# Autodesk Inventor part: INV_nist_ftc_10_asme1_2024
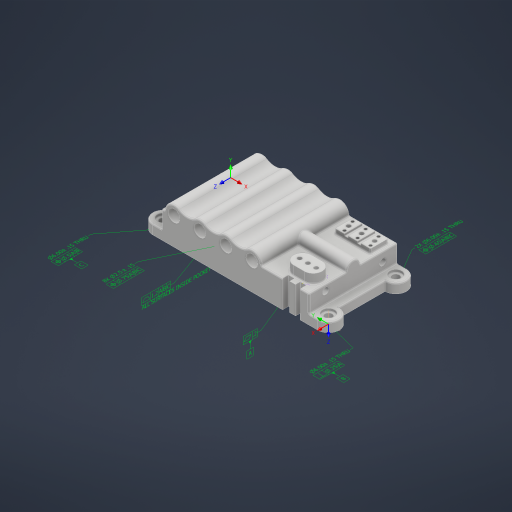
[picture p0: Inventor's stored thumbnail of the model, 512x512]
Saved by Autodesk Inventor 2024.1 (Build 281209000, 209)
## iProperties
Created: 2016-11
Part Number: INV_nist_ftc_10_asme1_2024
Material: Generic
Document SubType Name: Modeling
Designer: t_liuje
Density: 1 g/cm^3
Appearance: Default
Mass: 187.859 g
Surface Area: 487.851 cm^2
Volume: 187.859 cm^3
Author: t_liuje
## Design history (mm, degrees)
node "Tolerance Features"
  node "Planar Surface 1" dims "d273" = 6.78888 (derived), "d274" = 2.859 (derived), "d299" = 8.0955 (derived), "d300" = 2.22731 (derived), "d412" = 1.5 (derived), "d413" = 0 (derived), "d414" = 0 (derived), "d997" = -2.48442 (derived), "d998" = 10 (derived), "d999" = 0 (derived), "d1001" = 0.25 (derived), "d1002" = 0 (derived), "d1003" = 0 (derived), "d1004" = -22.09829 (derived), "d1005" = 10 (derived), "d1006" = 0 (derived), "d1008" = 0.5 (derived), "d1009" = 0 (derived), "d1010" = 0 (derived), "d1011" = -21.00192 (derived), "d1012" = 10 (derived), "d1013" = 0 (derived), "d1015" = 0.65 (derived), "d1016" = 0 (derived)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
  node "Datum Reference Frame 1"
  node "Simple Hole 1" dims "d273" = 6.78888 (derived), "d274" = 2.859 (derived), "d299" = 8.0955 (derived), "d300" = 2.22731 (derived), "d412" = 1.5 (derived), "d413" = 0 (derived), "d414" = 0 (derived), "d997" = -2.48442 (derived), "d998" = 10 (derived), "d999" = 0 (derived), "d1001" = 0.25 (derived), "d1002" = 0 (derived), "d1003" = 0 (derived), "d1004" = -22.09829 (derived), "d1005" = 10 (derived), "d1006" = 0 (derived), "d1008" = 0.5 (derived), "d1009" = 0 (derived), "d1010" = 0 (derived), "d1011" = -21.00192 (derived), "d1012" = 10 (derived), "d1013" = 0 (derived), "d1015" = 0.65 (derived), "d1016" = 0 (derived)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
  node "Datum Reference Frame 2"
  node "Simple Hole 2" dims "d273" = 6.78888 (derived), "d274" = 2.859 (derived), "d299" = 8.0955 (derived), "d300" = 2.22731 (derived), "d412" = 1.5 (derived), "d413" = 0 (derived), "d414" = 0 (derived), "d997" = -2.48442 (derived), "d998" = 10 (derived), "d999" = 0 (derived), "d1001" = 0.25 (derived), "d1002" = 0 (derived), "d1003" = 0 (derived), "d1004" = -22.09829 (derived), "d1005" = 10 (derived), "d1006" = 0 (derived), "d1008" = 0.5 (derived), "d1009" = 0 (derived), "d1010" = 0 (derived), "d1011" = -21.00192 (derived), "d1012" = 10 (derived), "d1013" = 0 (derived), "d1015" = 0.65 (derived), "d1016" = 0 (derived)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
  node "Datum Reference Frame 3"
  node "General Group 1"
  node "Coplanar Group 1" dims "d273" = 6.78888 (derived), "d274" = 2.859 (derived), "d299" = 8.0955 (derived), "d300" = 2.22731 (derived), "d412" = 1.5 (derived), "d413" = 0 (derived), "d414" = 0 (derived), "d997" = -2.48442 (derived), "d998" = 10 (derived), "d999" = 0 (derived), "d1001" = 0.25 (derived), "d1002" = 0 (derived), "d1003" = 0 (derived), "d1004" = -22.09829 (derived), "d1005" = 10 (derived), "d1006" = 0 (derived), "d1008" = 0.5 (derived), "d1009" = 0 (derived), "d1010" = 0 (derived), "d1011" = -21.00192 (derived), "d1012" = 10 (derived), "d1013" = 0 (derived), "d1015" = 0.65 (derived), "d1016" = 0 (derived)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
  node "Datum Reference Frame 4"
  node "Datum Reference Frame 5"
  node "Simple Hole 13" dims "d273" = 6.78888 (derived), "d274" = 2.859 (derived), "d299" = 8.0955 (derived), "d300" = 2.22731 (derived), "d412" = 1.5 (derived), "d413" = 0 (derived), "d414" = 0 (derived), "d997" = -2.48442 (derived), "d998" = 10 (derived), "d999" = 0 (derived), "d1001" = 0.25 (derived), "d1002" = 0 (derived), "d1003" = 0 (derived), "d1004" = -22.09829 (derived), "d1005" = 10 (derived), "d1006" = 0 (derived), "d1008" = 0.5 (derived), "d1009" = 0 (derived), "d1010" = 0 (derived), "d1011" = -21.00192 (derived), "d1012" = 10 (derived), "d1013" = 0 (derived), "d1015" = 0.65 (derived), "d1016" = 0 (derived)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
  node "Datum Reference Frame 6"
  node "Datum Reference Frame 12"
  node "Simple Hole 14" dims "d273" = 6.78888 (derived), "d274" = 2.859 (derived), "d299" = 8.0955 (derived), "d300" = 2.22731 (derived), "d412" = 1.5 (derived), "d413" = 0 (derived), "d414" = 0 (derived), "d997" = -2.48442 (derived), "d998" = 10 (derived), "d999" = 0 (derived), "d1001" = 0.25 (derived), "d1002" = 0 (derived), "d1003" = 0 (derived), "d1004" = -22.09829 (derived), "d1005" = 10 (derived), "d1006" = 0 (derived), "d1008" = 0.5 (derived), "d1009" = 0 (derived), "d1010" = 0 (derived), "d1011" = -21.00192 (derived), "d1012" = 10 (derived), "d1013" = 0 (derived), "d1015" = 0.65 (derived), "d1016" = 0 (derived)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
  node "Datum Reference Frame 7"
  node "Datum Reference Frame 18"
  node "Datum Reference Frame 23"
  node "Datum Reference Frame 13"
  node "Simple Hole 15" dims "d273" = 6.78888 (derived), "d274" = 2.859 (derived), "d299" = 8.0955 (derived), "d300" = 2.22731 (derived), "d412" = 1.5 (derived), "d413" = 0 (derived), "d414" = 0 (derived), "d997" = -2.48442 (derived), "d998" = 10 (derived), "d999" = 0 (derived), "d1001" = 0.25 (derived), "d1002" = 0 (derived), "d1003" = 0 (derived), "d1004" = -22.09829 (derived), "d1005" = 10 (derived), "d1006" = 0 (derived), "d1008" = 0.5 (derived), "d1009" = 0 (derived), "d1010" = 0 (derived), "d1011" = -21.00192 (derived), "d1012" = 10 (derived), "d1013" = 0 (derived), "d1015" = 0.65 (derived), "d1016" = 0 (derived)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
  node "Datum Reference Frame 8"
  node "Datum Reference Frame 19"
  node "Datum Reference Frame 14"
  node "Planar Surface 10" dims "d273" = 6.78888 (derived), "d274" = 2.859 (derived), "d299" = 8.0955 (derived), "d300" = 2.22731 (derived), "d412" = 1.5 (derived), "d413" = 0 (derived), "d414" = 0 (derived), "d997" = -2.48442 (derived), "d998" = 10 (derived), "d999" = 0 (derived), "d1001" = 0.25 (derived), "d1002" = 0 (derived), "d1003" = 0 (derived), "d1004" = -22.09829 (derived), "d1005" = 10 (derived), "d1006" = 0 (derived), "d1008" = 0.5 (derived), "d1009" = 0 (derived), "d1010" = 0 (derived), "d1011" = -21.00192 (derived), "d1012" = 10 (derived), "d1013" = 0 (derived), "d1015" = 0.65 (derived), "d1016" = 0 (derived)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
  node "Datum Reference Frame 9"
  node "Parallel Axes Pattern 3"
  node "Coplanar Group 2"
  node "Parallel Axes Pattern 5"
  node "Slot 1" dims "d273" = 6.78888 (derived), "d274" = 2.859 (derived), "d299" = 8.0955 (derived), "d300" = 2.22731 (derived), "d412" = 1.5 (derived), "d413" = 0 (derived), "d414" = 0 (derived), "d997" = -2.48442 (derived), "d998" = 10 (derived), "d999" = 0 (derived), "d1001" = 0.25 (derived), "d1002" = 0 (derived), "d1003" = 0 (derived), "d1004" = -22.09829 (derived), "d1005" = 10 (derived), "d1006" = 0 (derived), "d1008" = 0.5 (derived), "d1009" = 0 (derived), "d1010" = 0 (derived), "d1011" = -21.00192 (derived), "d1012" = 10 (derived), "d1013" = 0 (derived), "d1015" = 0.65 (derived), "d1016" = 0 (derived)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
  node "Datum Reference Frame 16"
  node "Datum Reference Frame 17"
  node "Slab 1"
  node "Parallel Axes Pattern 6"
  node "Cylindrical Surface 10"
  node "Simple Hole 51"
  node "Extruded Group 1"
  node "Simple Hole 63"
  node "Parallel Axes Pattern 12"
  node "Parallel Axes Pattern 13"
sketch "Sketch1"
  geometry: L1 (-62.5, 23)-(-62.5, 0); L2 (-62.5, 23)-(-22, 23); L3 (-62.5, 0)-(62.5, 0); L4 (62.5, 23)-(60, 23); L5 (62.5, 0)-(62.5, 23); L6 (80.303, 0)-(-60.812, 0); L7 (0, 48.078)-(0, -29.626); C1 r 3.5 at (-14, 23); C2 r 3.5 at (8, 23); C3 r 3.5 at (30, 23); C4 r 3.5 at (52, 23); A1 r 8 centre (-14, 23) between (-9.707, 29.751) and (-22, 23); A2 r 12.5 centre (-3, 40.299) between (-9.707, 29.751) and (3.707, 29.751); A3 r 8 centre (8, 23) between (12.293, 29.751) and (3.707, 29.751); A4 r 12.5 centre (19, 40.299) between (12.293, 29.751) and (25.707, 29.751); A5 r 8 centre (30, 23) between (34.293, 29.751) and (25.707, 29.751); A6 r 12.5 centre (41, 40.299) between (34.293, 29.751) and (47.707, 29.751); A7 r 8 centre (52, 23) between (60, 23) and (47.707, 29.751); 1 further point
  constraints: 14 end point, 14 point on circle, 11 centre point, 8 equal radius, 7 point on line, 6 tangent, 4 coincident, 2 collinear, 2 horizontal, 2 vertical, 1 other
  dimensions: "d0" = 125 distance of L1.end L3.end; "d1" = 10.5 distance from line of L5 A7.centre; "d2" = 23 distance of L1.start L1.end; "d3" = 8 radius of A7; "d4" = 22 distance of C3.centre C4.centre (= d5); "d5" = 22 distance of A1.centre A3.centre; "d6" = 22 distance of C3.centre A3.centre (= d5); "d7" = 12.5 radius of A6; "d8" = 7 diameter of C4
extrude "Extrusion1" new body sketch "Sketch1" stored distance "d9" = 75; taper "d10" = 0 deg
sketch "Sketch2"
  geometry: L1 (125, 0)-(125, -75) reference; L2 (0, 0)-(125, 0) reference; L3 (0, -75)-(0, 0) reference; L4 (125, -75)-(0, -75) reference; L5 (125, 0)-(132.5, 0); L6 (132.5, -18)-(132.5, -57); L7 (132.5, -75)-(125, -75); L8 (125, -75)-(125, 0); L9 (0, 0)-(-7.5, 0); L10 (-7.5, -18)-(-7.5, -57); L11 (-7.5, -75)-(0, -75); L12 (0, -75)-(0, 0); A1 r 9 centre (132.5, -9) between (132.5, -18) and (132.5, 0); A2 r 9 centre (132.5, -66) between (132.5, -75) and (132.5, -57); A3 r 9 centre (-7.5, -9) between (-7.5, 0) and (-7.5, -18); A4 r 9 centre (-7.5, -66) between (-7.5, -57) and (-7.5, -75); 1 further point
  constraints: 16 end point, 8 point on circle, 4 centre point, 4 parallel, 4 point on line, 4 tangent, 3 equal radius, 2 collinear, 2 horizontal, 2 perpendicular
  dimensions: "d11" = 7.5 distance of L1.start L5.end; "d12" = 18 distance of L6.start L5.end; "d13" = 18 distance of L6.end L7.start
extrude "Extrusion2" join sketch "Sketch2" distance "d14" = 8; taper "d15" = 0 deg
sketch "Sketch3"
  geometry: L1 (21, -53.5)-(30, -53.5); L2 (30, -68.5)-(21, -68.5); L3 (40.5, -75)-(0, -75) reference; L4 (40.5, 0)-(40.5, -75) reference; A1 r 7.5 centre (30, -61) between (30, -68.5) and (30, -53.5); A2 r 7.5 centre (21, -61) between (21, -53.5) and (21, -68.5); 1 further point
  constraints: 4 end point, 4 point on circle, 4 tangent, 2 centre point, 1 horizontal, 1 parallel
  dimensions: "d16" = 9 distance of L2.start L2.end; "d17" = 15 distance of L1.end L2.start; "d18" = 6.5 distance between parallel lines of L3 L2; "d19" = 10.5 distance from line of L4 A1.centre
extrude "Extrusion3" join sketch "Sketch3" distance "d20" = 8; taper "d21" = 0 deg
sketch "Sketch4"
  geometry: L1 (33, -75)-(33, -70); L2 (33, -70)-(28, -70); L3 (28, -70)-(28, -74); L4 (28, -74)-(23, -74); L5 (23, -74)-(23, -70); L6 (23, -70)-(18, -70); L7 (18, -70)-(18, -75); L8 (18, -75)-(33, -75); L9 (40.5, -75)-(0, -75) reference; L10 (40.5, 0)-(40.5, -75) reference; 1 further point
  constraints: 16 end point, 5 perpendicular, 2 collinear, 2 point on line, 1 vertical
  dimensions: "d22" = 5 distance of L1.start L1.end; "d23" = 5 distance of L1.end L2.end; "d24" = 4 distance of L2.end L3.end; "d25" = 5 distance of L3.end L4.end; "d26" = 5 distance of L5.end L6.end; "d27" = 7.5 distance between parallel lines of L10 L1
extrude "Extrusion4" cut sketch "Sketch4" stored distance "d28" = 8; taper "d29" = 0 deg
sketch "Sketch5"
  geometry: L1 (7.5, -5)-(37.5, -5); L2 (37.5, -5)-(37.5, -20); L3 (37.5, -20)-(7.5, -20); L4 (7.5, -20)-(7.5, -5); L5 (0, 0)-(40.5, 0) reference; L6 (40.5, 0)-(40.5, -75) reference; 1 further point
  constraints: 8 end point, 2 parallel, 1 horizontal, 1 perpendicular
  dimensions: "d30" = 30 distance of L2.end L3.end; "d31" = 15 distance of L1.end L2.end; "d32" = 5 distance between parallel lines of L1 L5; "d33" = 3 distance between parallel lines of L2 L6
extrude "Extrusion5" join sketch "Sketch5" distance "d34" = 4; taper "d35" = 0 deg
sketch "Sketch6"
  geometry: L1 (7.5, -5)-(37.5, -5) reference; L2 (7.5, -20)-(7.5, -5) reference; L3 (37.5, -5)-(37.5, -20) reference; L4 (37.5, -20)-(7.5, -20) reference; L5 (15.5, -5)-(18.5, -5); L6 (18.5, -5)-(18.5, -20); L7 (18.5, -20)-(15.5, -20); L8 (15.5, -20)-(15.5, -5); L9 (26.5, -5)-(29.5, -5); L10 (29.5, -5)-(29.5, -20); L11 (29.5, -20)-(26.5, -20); L12 (26.5, -20)-(26.5, -5); 1 further point
  constraints: 16 end point, 4 parallel, 4 point on line, 2 horizontal, 2 perpendicular
  dimensions: "d36" = 3 distance between parallel lines of L10 L12; "d37" = 8 distance between parallel lines of L3 L10; "d38" = 8 distance between parallel lines of L12 L6; "d39" = 3 distance between parallel lines of L8 L6
extrude "Extrusion6" cut sketch "Sketch6" distance "d40" = 1.5; taper "d41" = 0 deg
sketch "Sketch7"
  geometry: L1 (0, 75)-(0, 0) reference; A1 r 6 centre (0, 37.5) between (0, 43.5) and (0, 31.5); 1 further point
  constraints: 2 point on circle, 2 point on line, 1 centre point, 1 midpoint
  dimensions: "d42" = 12 diameter of A1
extrude "Extrusion7" join sketch "Sketch7" stored distance "d43" = 1.5; taper "d44" = 0 deg
fillet "Fillet1" dims "d45" = 1
sketch "Sketch11"
  geometry: A1 r 9 centre (-132.5, -9) between (-132.5, 0) and (-132.5, -18) reference; 3 further points
  constraints: 2 coincident
hole "Hole2" sketch "Sketch11" diameter "d57" = 6; stored, may be unused: countersink angle "d61" = 90 deg, drill point angle "d63" = 0 deg; dims "d58" = 6, "d59" = 10, "d60" = 2, "d62" = 8
sketch "Sketch12"
  geometry: C1 r 3.5 at (-52, -23) reference; C2 r 3.5 at (-30, -23) reference; C3 r 3.5 at (-8, -23) reference; C4 r 3.5 at (14, -23) reference; 4 further points
  constraints: 4 coincident
hole "Hole6" sketch "Sketch12" diameter "d93" = 10; stored, may be unused: countersink angle "d97" = 90 deg, drill point angle "d99" = 0 deg; dims "d94" = 6, "d95" = 10, "d96" = 2, "d98" = 10
hole "Hole7" diameter "d102" = 3.5; stored, may be unused: countersink angle "d106" = 90 deg, drill point angle "d108" = 0 deg; dims "d100" = 14, "d101" = 8, "d103" = 6, "d104" = 10, "d105" = 2, "d107" = 10.25
pattern_linear "Rectangular Pattern1" dims "d111" = 7
sketch "Sketch15"
  geometry: L1 (37.5, -19)-(37.5, -6) reference; L2 (29.5, -20)-(36.5, -20) reference; L3 (29.5, -5)-(29.5, -20) reference; L4 (29.5, -5)-(29.5, -20) reference; L5 (29.5, -16.191)-(37.5, -16.191); L6 (33.5, -16.191)-(33.5, -8.753); L7 (29.5, -12.5)-(36.185, -12.5); L8 (29.5, -20)-(29.5, -5); 2 further points
  constraints: 8 end point, 2 midpoint, 2 point on line, 2 symmetric about line, 1 horizontal, 1 perpendicular, 1 vertical
  dimensions: "d121" = 2.4 distance from line of L1 point (35.1, -17.5); "d122" = 2.5 distance from line of L2 point (35.1, -17.5)
hole "Hole9" sketch "Sketch15" at (35.1, -17.5), (31.9, -7.5) diameter "d123" = 2.459; stored, may be unused: countersink angle "d127" = 90 deg, drill point angle "d129" = 118 deg; dims "d124" = 6, "d125" = 10, "d126" = 2, "d128" = 12
sketch "Sketch8"
  geometry: L1 (-12, -5.5)-(-90, -5.5); L2 (-90, -5.5)-(-90, 44.5); L3 (-90, 44.5)-(-12, 44.5); L4 (-12, 44.5)-(-12, -5.5); L5 (0, 0)-(0, 39) reference; L6 (-110, -18)-(0, -18) reference; 1 further point
  constraints: 8 end point, 2 parallel, 1 horizontal, 1 perpendicular
  dimensions: "d142" = 78 distance of L2.end L3.end; "d143" = 50 distance of L1.end L2.end; "d144" = 12 distance between parallel lines of L5 L4; "d145" = 12.5 distance between parallel lines of L1 L6
extrude "Extrusion8" cut sketch "Sketch8" distance "d146" = 17; taper "d147" = 0 deg
fillet "Fillet2" dims "d148" = 2
hole "Hole11" diameter "d151" = 2.5; stored, may be unused: countersink angle "d155" = 90 deg, drill point angle "d157" = 118 deg; dims "d149" = 22, "d150" = 18, "d152" = 6, "d153" = 10, "d154" = 2, "d156" = 12
pattern_linear "Rectangular Pattern3" dims "d160" = 22, "d163" = 31
hole "Hole12" diameter "d287" = 5.5; stored, may be unused: countersink angle "d291" = 90 deg, drill point angle "d293" = 118 deg; dims "d285" = 14, "d286" = 5, "d288" = 6, "d289" = 4, "d290" = 2, "d292" = 27.5
hole "Hole13" diameter "d330" = 5.5; stored, may be unused: countersink angle "d334" = 90 deg, drill point angle "d336" = 118 deg; dims "d328" = 8.062, "d329" = 12.54, "d331" = 6, "d332" = 4, "d333" = 2, "d335" = 35
workplane "Work Plane2"
sketch "Sketch9"
  geometry: L1 (-26.77, 0)-(-11.77, 0)
  constraints: 2 end point, 1 horizontal
  dimensions: "d370" = 15 distance of L1.start L1.end
workplane "Work Plane3"
workplane "Work Plane4"
workplane "Work Plane5"
workplane "Work Plane6"
workplane "Work Plane7"
workplane "Work Plane8"
fillet "Fillet3" dims "d870" = 0.15
sketch "Sketch30"
  geometry: 3 further points
sketch "Sketch28"
  geometry: L1 (0, 0)-(0, 39) reference; L2 (-110, -18)-(0, -18) reference; C1 r 1.25 at (-18, 4); 2 further points
  constraints: 1 centre point, 1 coincident
  dimensions: "d1520" = 18 distance from line of L1 point (-18, 4); "d1521" = 22 distance from line of L2 point (-18, 4); "d1522" = 2.5 diameter of C1
extrude "Extrusion13" cut sketch "Sketch28" stored distance "d1523" = 10; taper "d1524" = 0 deg
pattern_linear "Rectangular Pattern4" dims "d1527" = 22, "d1530" = 31
sketch "Sketch13"
  geometry: C1 r 3.5 at (14, 23) reference; C2 r 3.5 at (-8, 23) reference; C3 r 3.5 at (-30, 23) reference; C4 r 3.5 at (-52, 23) reference; 5 further points
  constraints: 4 coincident
hole "Hole14" sketch "Sketch13" diameter "d901" = 10; stored, may be unused: countersink angle "d905" = 90 deg, drill point angle "d907" = 0 deg; dims "d902" = 6, "d903" = 4, "d904" = 2, "d906" = 10
mirror "Mirror3"
sketch "Sketch14"
  geometry: C1 r 3 at (7.5, -9) reference; C2 r 3 at (-132.5, -9) reference; C3 r 3 at (-132.5, -9) reference; C4 r 3 at (7.5, -9) reference; C5 r 3 at (-132.5, -66) reference; C6 r 3 at (7.5, -66) reference; 5 further points
  constraints: 4 coincident
hole "Hole15" sketch "Sketch14" diameter "d908" = 10; stored, may be unused: countersink angle "d912" = 90 deg, drill point angle "d914" = 0 deg; dims "d909" = 6, "d910" = 4, "d911" = 2, "d913" = 2
fillet "Fillet4" dims "d875" = 0.2
sketch "Sketch16"
  geometry: L1 (26.5, -19)-(26.5, -6); L2 (7.5, -20)-(25.5, -20); L3 (29.5, -20)-(26.5, -20) reference; L4 (18.5, -20)-(26.5, -20) reference; L5 (26.5, -5)-(18.5, -5) reference; L6 (18.5, -5)-(18.5, -20) reference; 3 further points
  constraints: 4 end point
  dimensions: "d915" = 2.4 distance from line of L1 point (24.1, -17.5); "d916" = 2.5 distance from line of L2 point (24.1, -17.5); "d917" = 2.5 distance from line of L5 point (20.9, -7.5); "d918" = 2.4 distance from line of L6 point (20.9, -7.5)
hole "Hole16" sketch "Sketch16" at (24.1, -17.5), (20.9, -7.5) diameter "d919" = 2.459; stored, may be unused: countersink angle "d923" = 90 deg, drill point angle "d925" = 118 deg; dims "d920" = 6, "d921" = 4, "d922" = 2, "d924" = 12
sketch "Sketch17"
  geometry: L1 (37.5, -19)-(37.5, -6); L2 (29.5, -20)-(36.5, -20); L3 (29.5, -5)-(29.5, -20); L4 (29.5, -5)-(29.5, -20); L5 (29.5, -16.191)-(37.5, -16.191); L6 (33.5, -16.191)-(33.5, -8.753); L7 (29.5, -12.5)-(36.185, -12.5); L8 (29.5, -20)-(29.5, -5); L9 (15.5, -19)-(15.5, -6); L10 (7.5, -20)-(14.5, -20); L11 (29.5, -20)-(26.5, -20); L12 (7.5, -20)-(15.5, -20); L13 (15.5, -5)-(7.5, -5); L14 (7.5, -5)-(7.5, -20); L15 (15.5, -20)-(15.5, -5) reference; C1 r 1.75 at (22.5, -12.5); 7 further points
  constraints: 28 end point, 2 midpoint, 2 point on line, 2 symmetric about line, 1 centre point, 1 coincident, 1 horizontal, 1 perpendicular, 1 vertical
  dimensions: "d926" = 2.4 distance from line of L1 point (35.1, -17.5); "d927" = 2.5 distance from line of L2 point (35.1, -17.5); "d928" = 2.4 distance from line of L9 point (13.1, -17.5); "d929" = 2.5 distance from line of L10 point (13.1, -17.5); "d930" = 2.5 distance from line of L13 point (9.9, -7.5); "d931" = 2.4 distance from line of L14 point (9.9, -7.5); "d1066" = 3.5 diameter of C1 (derived)
hole "Hole17" sketch "Sketch17" diameter "d932" = 2.459; stored, may be unused: countersink angle "d936" = 90 deg, drill point angle "d938" = 118 deg; dims "d933" = 6, "d934" = 4, "d935" = 2, "d937" = 12
sketch "Sketch18" dims "d944" = 10
  geometry: L1 (29.5, -20)-(36.5, -20) reference; L2 (37.5, -19)-(37.5, -6) reference; C1 r 1.75 at (11.5, -12.5); C2 r 1.75 at (33.5, -12.5); 3 further points
  constraints: 2 centre point, 2 coincident, 1 horizontal, 2 other
  dimensions: "d112" = 7.5 distance from line of L1 point (33.5, -12.5); "d113" = 4 distance from line of L2 point (33.5, -12.5); "d941" = 11 distance of point (33.5, -12.5) point (22.5, -12.5); "d1056" = 3.5 diameter of C1; "d1069" = 3.5 diameter of C2
extrude "Extrusion10" cut sketch "Sketch18" distance "d1057" = 9.25; taper "d1058" = 0 deg
extrude "Extrusion11" cut sketch "Sketch17" distance "d1067" = 9.25; taper "d1068" = 0 deg
extrude "Extrusion12" cut sketch "Sketch18" distance "d1070" = 9.25; taper "d1071" = 0 deg
sketch "Sketch20"
  geometry: L1 (-1.061, 8)-(5.303, 8) reference; L2 (3.544, 8)-(-4.428, 8); L3 (-4.428, 8)-(-4.428, -0.058); L4 (-4.428, -0.058)-(3.544, -0.058); L5 (3.544, -0.058)-(3.544, 8); 1 further point
  constraints: 8 end point, 2 parallel, 1 horizontal, 1 perpendicular, 1 point on line
patch "Boundary Patch1" sketch "Sketch20"
sketch "Sketch21"
  geometry: L1 (7.5, 8)-(-5.303, 8) reference; L2 (-8.827, 0)-(18.436, 0) reference; L3 (-1.99, 8)-(4.804, 8); L4 (4.804, 8)-(4.804, 0); L5 (4.804, 0)-(-1.99, 0); L6 (-1.99, 0)-(-1.99, 8); 2 further points
  constraints: 8 end point, 2 parallel, 1 horizontal, 1 midpoint, 1 perpendicular, 1 point on line
patch "Boundary Patch2" sketch "Sketch21"
workplane "Work Plane10"
mirror "Mirror4"
mirror "Mirror5"
workpoint "Work Point1"
workaxis "Work Axis1"
workpoint "Work Point2"
workpoint "Work Point3"
workpoint "Work Point4"
sketch "Sketch27"
  geometry: 2 further points
sketch "Sketch29"
  geometry: C1 r 1.75 at (32.5, -61); C2 r 1.75 at (25.5, -61); C3 r 1.75 at (18.5, -61); 4 further points
  constraints: 3 centre point, 3 coincident
extrude "Extrusion14" cut sketch "Sketch29" stored distance "d1538" = 10; taper "d1539" = 0 deg
sketch "Sketch32"
  geometry: 3 further points
  constraints: 1 coincident
sketch "Sketch33"
  geometry: 4 further points
  constraints: 1 coincident
body "Solid1"
node "Annotations"
sketch "Sketch10"
  geometry: 1 further point
node "Projected Loop1"
body "Srf1"
body "Srf2"
body "Srf4"
body "Srf5"
patch "Boundary Patch3"
patch "Boundary Patch4"
node "Leader Text 3"
node "Leader Text 6"
node "General Note 1"
node "General Surface Profile Tolerance"
node "Hole Note 1" dims "d0" = 125
node "Feature Control Frame 31"
node "Datum Identifier 2" dims "d0" = 125, "d273" = 6.78888 (derived), "d274" = 2.859 (derived), "d299" = 8.0955 (derived), "d300" = 2.22731 (derived), "d412" = 1.5 (derived), "d413" = 0 (derived), "d414" = 0 (derived), "d997" = -2.48442 (derived), "d998" = 10 (derived), "d999" = 0 (derived), "d1001" = 0.25 (derived), "d1002" = 0 (derived), "d1003" = 0 (derived), "d1004" = -22.09829 (derived), "d1005" = 10 (derived), "d1006" = 0 (derived), "d1008" = 0.5 (derived), "d1009" = 0 (derived), "d1010" = 0 (derived), "d1011" = -21.00192 (derived), "d1012" = 10 (derived), "d1013" = 0 (derived), "d1015" = 0.65 (derived)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
node "Hole Note 2" dims "d0" = 125
node "Feature Control Frame 32"
node "Datum Identifier 3" dims "d0" = 125, "d273" = 6.78888 (derived), "d274" = 2.859 (derived), "d299" = 8.0955 (derived), "d300" = 2.22731 (derived), "d412" = 1.5 (derived), "d413" = 0 (derived), "d414" = 0 (derived), "d997" = -2.48442 (derived), "d998" = 10 (derived), "d999" = 0 (derived), "d1001" = 0.25 (derived), "d1002" = 0 (derived), "d1003" = 0 (derived), "d1004" = -22.09829 (derived), "d1005" = 10 (derived), "d1006" = 0 (derived), "d1008" = 0.5 (derived), "d1009" = 0 (derived), "d1010" = 0 (derived), "d1011" = -21.00192 (derived), "d1012" = 10 (derived), "d1013" = 0 (derived), "d1015" = 0.65 (derived)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
node "Simple Hole 3"
node "Simple Hole 4"
node "Parallel Axes Pattern 1"
node "Hole Note 3" dims "d0" = 125
node "Feature Control Frame 33"
node "Diameter Dimension 1" dims "d0" = 125, "d1089" = 3.5 (derived)
node "Feature Control Frame 40"
node "Datum Identifier 5" dims "d0" = 125, "d273" = 6.78888 (derived), "d274" = 2.859 (derived), "d299" = 8.0955 (derived), "d300" = 2.22731 (derived), "d412" = 1.5 (derived), "d413" = 0 (derived), "d414" = 0 (derived), "d997" = -2.48442 (derived), "d998" = 10 (derived), "d999" = 0 (derived), "d1001" = 0.25 (derived), "d1002" = 0 (derived), "d1003" = 0 (derived), "d1004" = -22.09829 (derived), "d1005" = 10 (derived), "d1006" = 0 (derived), "d1008" = 0.5 (derived), "d1009" = 0 (derived), "d1010" = 0 (derived), "d1011" = -21.00192 (derived), "d1012" = 10 (derived), "d1013" = 0 (derived), "d1015" = 0.65 (derived)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
node "Diameter Dimension 2" dims "d0" = 125, "d1099" = 3.5 (derived)
node "Feature Control Frame 41"
node "Datum Identifier 6" dims "d0" = 125, "d273" = 6.78888 (derived), "d274" = 2.859 (derived), "d299" = 8.0955 (derived), "d300" = 2.22731 (derived), "d412" = 1.5 (derived), "d413" = 0 (derived), "d414" = 0 (derived), "d997" = -2.48442 (derived), "d998" = 10 (derived), "d999" = 0 (derived), "d1001" = 0.25 (derived), "d1002" = 0 (derived), "d1003" = 0 (derived), "d1004" = -22.09829 (derived), "d1005" = 10 (derived), "d1006" = 0 (derived), "d1008" = 0.5 (derived), "d1009" = 0 (derived), "d1010" = 0 (derived), "d1011" = -21.00192 (derived), "d1012" = 10 (derived), "d1013" = 0 (derived), "d1015" = 0.65 (derived)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
node "Diameter Dimension 3" dims "d0" = 125, "d1109" = 3.5 (derived)
node "Feature Control Frame 42"
node "Datum Identifier 7" dims "d0" = 125, "d273" = 6.78888 (derived), "d274" = 2.859 (derived), "d299" = 8.0955 (derived), "d300" = 2.22731 (derived), "d412" = 1.5 (derived), "d413" = 0 (derived), "d414" = 0 (derived), "d997" = -2.48442 (derived), "d998" = 10 (derived), "d999" = 0 (derived), "d1001" = 0.25 (derived), "d1002" = 0 (derived), "d1003" = 0 (derived), "d1004" = -22.09829 (derived), "d1005" = 10 (derived), "d1006" = 0 (derived), "d1008" = 0.5 (derived), "d1009" = 0 (derived), "d1010" = 0 (derived), "d1011" = -21.00192 (derived), "d1012" = 10 (derived), "d1013" = 0 (derived), "d1015" = 0.65 (derived)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
node "Feature Control Frame 43"
node "Datum Identifier 8" dims "d0" = 125, "d273" = 6.78888 (derived), "d274" = 2.859 (derived), "d299" = 8.0955 (derived), "d300" = 2.22731 (derived), "d412" = 1.5 (derived), "d413" = 0 (derived), "d414" = 0 (derived), "d997" = -2.48442 (derived), "d998" = 10 (derived), "d999" = 0 (derived), "d1001" = 0.25 (derived), "d1002" = 0 (derived), "d1003" = 0 (derived), "d1004" = -22.09829 (derived), "d1005" = 10 (derived), "d1006" = 0 (derived), "d1008" = 0.5 (derived), "d1009" = 0 (derived), "d1010" = 0 (derived), "d1011" = -21.00192 (derived), "d1012" = 10 (derived), "d1013" = 0 (derived), "d1015" = 0.65 (derived)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
node "Planar Surface 13"
node "Planar Surface 14"
node "Feature Control Frame 45"
node "Leader Text 10"
node "Planar Surface 16"
node "Planar Surface 17"
node "Linear Dimension 1" dims "d0" = 125, "d1217" = 15 (derived)
node "Feature Control Frame 51"
node "Datum Identifier 11" dims "d0" = 125, "d273" = 6.78888 (derived), "d274" = 2.859 (derived), "d299" = 8.0955 (derived), "d300" = 2.22731 (derived), "d412" = 1.5 (derived), "d413" = 0 (derived), "d414" = 0 (derived), "d997" = -2.48442 (derived), "d998" = 10 (derived), "d999" = 0 (derived), "d1001" = 0.25 (derived), "d1002" = 0 (derived), "d1003" = 0 (derived), "d1004" = -22.09829 (derived), "d1005" = 10 (derived), "d1006" = 0 (derived), "d1008" = 0.5 (derived), "d1009" = 0 (derived), "d1010" = 0 (derived), "d1011" = -21.00192 (derived), "d1012" = 10 (derived), "d1013" = 0 (derived), "d1015" = 0.65 (derived)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
node "Planar Surface 18"
node "Planar Surface 19"
node "Linear Dimension 2" dims "d0" = 125, "d1250" = 5 (derived)
node "Feature Control Frame 52"
node "Feature Control Frame 54"
node "Simple Hole 41"
node "Simple Hole 42"
node "Parallel Axes Pattern 7"
node "Hole Note 13" dims "d0" = 125
node "Feature Control Frame 58"
node "Simple Hole 43"
node "Simple Hole 44"
node "Parallel Axes Pattern 8"
node "Hole Note 14" dims "d0" = 125
node "Feature Control Frame 59"
node "Simple Hole 45"
node "Simple Hole 46"
node "Parallel Axes Pattern 9"
node "Hole Note 15" dims "d0" = 125
node "Feature Control Frame 60"
node "Simple Hole 47"
node "Simple Hole 48"
node "Simple Hole 49"
node "Simple Hole 50"
node "Parallel Axes Pattern 10"
node "Diameter Dimension 7" dims "d0" = 125, "d1339" = 7 (derived)
node "Feature Control Frame 61"
node "Radial Dimension 1" dims "d0" = 125, "d1345" = 0.2 (derived)
node "Planar Surface 20"
node "Cylindrical Surface 11"
node "Planar Surface 21"
node "Cylindrical Surface 12"
node "Feature Control Frame 65"
node "Planar Surface 26"
node "Planar Surface 27"
node "Cylindrical Surface 13"
node "Cylindrical Surface 14"
node "Cylindrical Surface 15"
node "Spherical Surface 1"
node "Planar Surface 28"
node "Cylindrical Surface 16"
node "Planar Surface 29"
node "Cylindrical Surface 17"
node "Spherical Surface 2"
node "Cylindrical Surface 18"
node "Cylindrical Surface 19"
node "Planar Surface 30"
node "Spherical Surface 3"
node "Spherical Surface 4"
node "Cylindrical Surface 20"
node "Feature Control Frame 68"
node "Leader Text 23"
node "Feature Control Frame 71"
node "Datum Identifier 12" dims "d0" = 125, "d273" = 6.78888 (derived), "d274" = 2.859 (derived), "d299" = 8.0955 (derived), "d300" = 2.22731 (derived), "d412" = 1.5 (derived), "d413" = 0 (derived), "d414" = 0 (derived), "d997" = -2.48442 (derived), "d998" = 10 (derived), "d999" = 0 (derived), "d1001" = 0.25 (derived), "d1002" = 0 (derived), "d1003" = 0 (derived), "d1004" = -22.09829 (derived), "d1005" = 10 (derived), "d1006" = 0 (derived), "d1008" = 0.5 (derived), "d1009" = 0 (derived), "d1010" = 0 (derived), "d1011" = -21.00192 (derived), "d1012" = 10 (derived), "d1013" = 0 (derived), "d1015" = 0.65 (derived)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
node "Simple Hole 64"
node "Simple Hole 65"
node "Simple Hole 66"
node "Simple Hole 67"
node "Hole Note 22" dims "d0" = 125
node "Feature Control Frame 72"
node "Leader Text 25"
node "Radial Dimension 2" dims "d0" = 125, "d1478" = 0.15 (derived)
node "Simple Hole 68"
node "Simple Hole 69"
node "Simple Hole 70"
node "Simple Hole 71"
node "Hole Note 23" dims "d0" = 125
node "Feature Control Frame 73"
node "Hole Note 16" dims "d0" = 125
node "Feature Control Frame 74"
node "Planar Surface 31"
node "Planar Surface 32"
node "Planar Surface 33"
node "Feature Control Frame 75"
node "Datum Identifier 13" dims "d0" = 125, "d273" = 6.78888 (derived), "d274" = 2.859 (derived), "d299" = 8.0955 (derived), "d300" = 2.22731 (derived), "d412" = 1.5 (derived), "d413" = 0 (derived), "d414" = 0 (derived), "d997" = -2.48442 (derived), "d998" = 10 (derived), "d999" = 0 (derived), "d1001" = 0.25 (derived), "d1002" = 0 (derived), "d1003" = 0 (derived), "d1004" = -22.09829 (derived), "d1005" = 10 (derived), "d1006" = 0 (derived), "d1008" = 0.5 (derived), "d1009" = 0 (derived), "d1010" = 0 (derived), "d1011" = -21.00192 (derived), "d1012" = 10 (derived), "d1013" = 0 (derived), "d1015" = 0.65 (derived)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
node "Leader Text 26"
node "Hole Note 21" dims "d0" = 125
node "Feature Control Frame 76"
node "Simple Hole 75"
node "Simple Hole 76"
node "Simple Hole 77"
node "Simple Hole 78"
node "Hole Note 27" dims "d0" = 125
node "Feature Control Frame 78"
node "Leader Text 27"
node "Simple Hole 79"
node "Simple Hole 80"
node "Simple Hole 81"
node "Simple Hole 82"
node "Simple Hole 83"
node "Simple Hole 84"
node "Simple Hole 85"
node "Simple Hole 86"
node "Diameter Dimension 8" dims "d0" = 125, "d1534" = 2.5 (derived)
node "Feature Control Frame 79"
node "Simple Hole 87"
node "Simple Hole 88"
node "Simple Hole 89"
node "Diameter Dimension 9" dims "d0" = 125, "d1543" = 3.5 (derived)
node "Feature Control Frame 80"
other parameters: "d410" = 45 deg, "d411" = -45 deg, "d415" = 0, "d416" = 0, "d417" = 0, "d418" = -90 deg, "d419" = 0, "d420" = 0, "d960" = 0, "d961" = 0, "d962" = 0, "d963" = 0, "d964" = 0, "d965" = 0, "d966" = 0, "d967" = 0, "d968" = 0, "d969" = 0, "d970" = 0, "d971" = 0, "d972" = 0, "d973" = 0, "d974" = 0, "d975" = 0, "d976" = 0, "d977" = 0, "d1464" = 0, "d1465" = 0, "d1466" = 0, "d1467" = -90 deg, "d1468" = 0, "d1469" = 0, "d1553" = 0, "d1554" = 0, "d1555" = 0, "d1556" = 0, "d1557" = 0, "d1558" = -90 deg, "d1559" = 0, "d1560" = 0, "d1561" = 0, "d1562" = 0, "d1563" = 0, "d1564" = -90 deg, "d1565" = 0, "d1566" = 0, "d1567" = 0, "d1568" = 0, "d1569" = 0, "d1570" = -90 deg, "d1571" = 0, "d1572" = 0, "d1573" = 0, "d1574" = 0, "d1575" = 0, "d1576" = -90 deg
